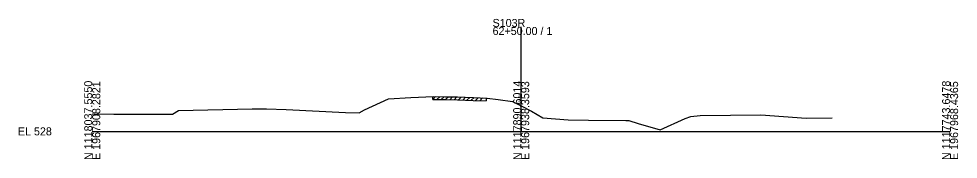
# Model space of a CAD drawing. Extents: x 974 to 1303, y 990 to 10019.
# Drawn here: x 974.3 to 1302.8, y 4990.3 to 5039.3 of the extents above; entities that cross this region are included whole.
import ezdxf

# ---------------------------------------------------------------- set-up
doc = ezdxf.new("R2010")
doc.units = 0
for name, color, linetype in [('Level 10', 7, 'Continuous'), ('Level 60', 7, 'Continuous'), ('Level 61', 7, 'Continuous'), ('Level 63', 7, 'Continuous')]:
    doc.layers.add(name, color=color, linetype=linetype)

msp = doc.modelspace()

# ---------------------------------------------------------------- linework, layer by layer
at = {"layer": 'Level 60'}
for p, q in [((1095.23, 5007.51), (1103.59, 5011.41)), ((1103.59, 5011.41), (1111.41, 5011.77)), ((1111.41, 5011.77), (1119.39, 5012.14)), ((1119.39, 5012.14), (1123.57, 5012.07)), ((1123.57, 5012.07), (1127.72, 5012)), ((1127.72, 5012), (1133.16, 5011.81)), ((1133.16, 5011.81), (1138.08, 5011.61)), ((1138.08, 5011.61), (1141.97, 5011.14)), ((1141.97, 5011.14), (1146.98, 5010.44)), ((1146.98, 5010.44), (1150, 5008.86)), ((1028.1, 5006.02), (1030.2, 5007.26)), ((1030.2, 5007.26), (1055.98, 5007.82)), ((1055.98, 5007.82), (1060.95, 5007.87)), ((1060.95, 5007.87), (1067.78, 5007.62)), ((1067.78, 5007.62), (1088.53, 5006.55)), ((1093.36, 5006.51), (1095.23, 5007.51)), ((1150, 5008.86), (1153.57, 5007)), ((1153.57, 5007), (1157.54, 5004.7)), ((1000, 5006.13), (1007.6, 5006.01)), ((1007.6, 5006.01), (1028.1, 5006.02)), ((1088.53, 5006.55), (1093.36, 5006.51)), ((1157.54, 5004.7), (1166.44, 5004.02)), ((1166.44, 5004.02), (1173.56, 5003.95)), ((1173.56, 5003.95), (1186.56, 5003.78)), ((1186.56, 5003.78), (1187.6, 5003.74)), ((1187.6, 5003.74), (1190.91, 5002.79)), ((1198.63, 5000.59), (1207.38, 5004.47)), ((1207.38, 5004.47), (1209.3, 5005.14)), ((1209.3, 5005.14), (1212.64, 5005.56)), ((1212.64, 5005.56), (1233.79, 5005.8)), ((1233.79, 5005.8), (1249.7, 5004.62)), ((1249.7, 5004.62), (1258.72, 5004.71)), ((1190.91, 5002.79), (1198.63, 5000.59))]:
    msp.add_line(p, q, dxfattribs=at)
at = {"layer": 'Level 61'}
for p, q in [((1119.05, 5011.12), (1120.06, 5012.13)), ((1119.05, 5011.12), (1119.05, 5012.12)), ((1119.05, 5011.12), (1119.39, 5011.14)), ((1119.39, 5011.14), (1123.57, 5011.07)), ((1120.55, 5011.12), (1121.54, 5012.1)), ((1122.05, 5011.1), (1123.04, 5012.08)), ((1123.55, 5011.07), (1124.54, 5012.06)), ((1123.57, 5011.07), (1127.72, 5011)), ((1125.05, 5011.05), (1126.04, 5012.03)), ((1126.55, 5011.02), (1127.54, 5012)), ((1127.72, 5011), (1133.16, 5010.81)), ((1128.05, 5010.99), (1129.02, 5011.96)), ((1129.55, 5010.94), (1130.52, 5011.9)), ((1131.05, 5010.88), (1132.02, 5011.85)), ((1132.55, 5010.83), (1133.52, 5011.8)), ((1133.16, 5010.81), (1137.73, 5010.62)), ((1134.05, 5010.77), (1135.01, 5011.73)), ((1135.55, 5010.71), (1136.51, 5011.67)), ((1137.73, 5011.62), (1137.73, 5010.62))]:
    msp.add_line(p, q, dxfattribs=at)
at = {"layer": 'Level 63'}
for p, q in [((1150, 5000), (1150, 5036.42)), ((1000, 5000), (1150, 5000)), ((1150, 5000), (1300, 5000))]:
    msp.add_line(p, q, dxfattribs=at)

# ---------------------------------------------------------------- texts
at = {"layer": 'Level 10'}
msp.add_text('536.86', height=0.9, rotation=90, dxfattribs=at).set_placement((1149.95, 5009.36))
at = {"layer": 'Level 63'}
for s, p in [('S103R', (1140, 5036.42)), ('62+50.00 / 1', (1140, 5033.62)), ('EL 528', (974, 4998.6))]:
    msp.add_text(s, height=2.8, dxfattribs=at).set_placement(p)
for s, p in [('N 1118037.5550', (1000, 4990)), ('E 1967908.2821', (1002.8, 4990)), ('N 1117890.6014', (1150, 4990)), ('E 1967938.3593', (1152.8, 4990)), ('N 1117743.6478', (1300, 4990)), ('E 1967968.4365', (1302.8, 4990))]:
    msp.add_text(s, height=2.8, rotation=90, dxfattribs=at).set_placement(p)

doc.saveas('drawing.dxf')
